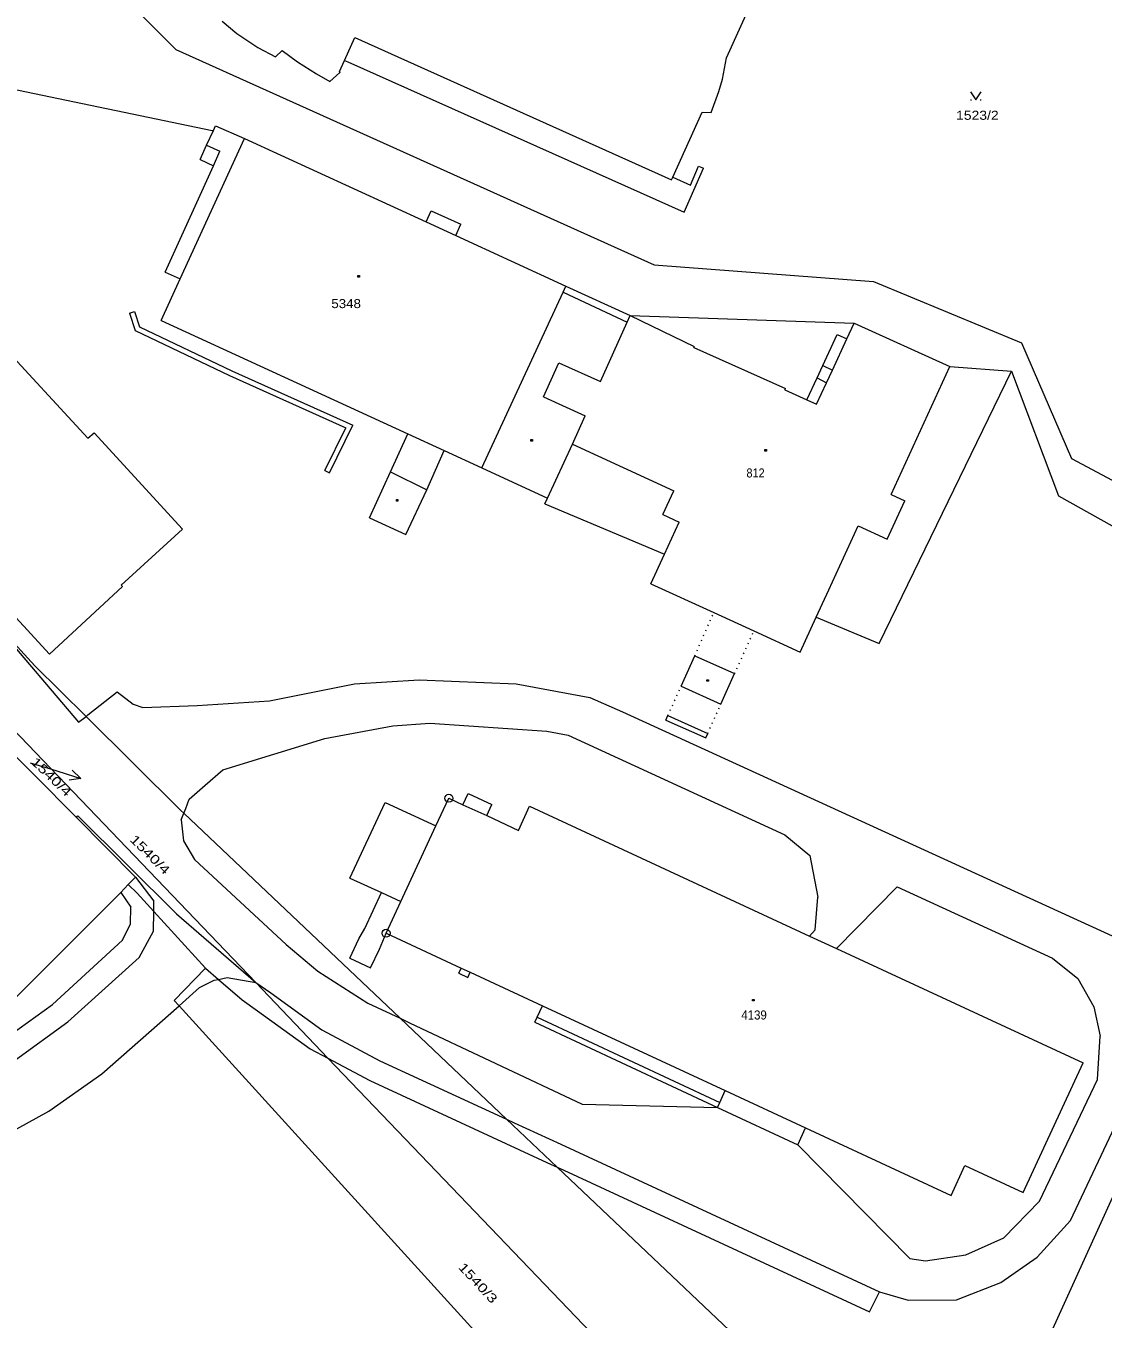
# Model space of a CAD drawing. Extents: x -630464 to -630140, y -1004543 to -1004208.
# Drawn here: x -630338.9 to -630237.7, y -1004467.8 to -1004346.3 of the extents above; entities that cross this region are included whole.
import ezdxf

# ---------------------------------------------------------------- set-up
doc = ezdxf.new("R2010")
doc.units = 0
doc.header["$LTSCALE"] = 0.34
doc.linetypes.add('DOTTED', pattern=[1.5, 0.3, -1.2])
for name, color, linetype, lineweight in [('1', 7, 'Continuous', 13), ('13', 7, 'Continuous', 13), ('16', 7, 'Continuous', 13), ('2', 7, 'Continuous', 13), ('23', 7, 'Continuous', 13), ('25', 7, 'Continuous', 13), ('28', 7, 'Continuous', 13)]:
    doc.layers.add(name, color=color, linetype=linetype, lineweight=lineweight)
doc.layers.add('14', color=7, linetype='Continuous')
doc.layers.add('15', color=7, linetype='Continuous')

msp = doc.modelspace()

# ---------------------------------------------------------------- linework, layer by layer
at = {"layer": '1'}
for p, q in [((-630317.08, -1004348.35), (-630315.44, -1004349.23)), ((-630313.38, -1004349.7), (-630311.59, -1004350.82)), ((-630309.41, -1004350.61), (-630309.38, -1004350.69)), ((-630274.53, -1004354.45), (-630273.8, -1004352.49)), ((-630273.8, -1004352.49), (-630273.46, -1004351.32)), ((-630278.12, -1004360.52), (-630275.37, -1004354.41)), ((-630275.37, -1004354.41), (-630274.53, -1004354.45)), ((-630321.38, -1004356.13), (-630321.27, -1004356.15)), ((-630325.81, -1004369.44), (-630321.27, -1004359.46)), ((-630322.52, -1004358.88), (-630321.27, -1004359.46)), ((-630277.04, -1004363.83), (-630275.24, -1004359.68)), ((-630298.51, -1004366.01), (-630298.03, -1004364.95)), ((-630298.51, -1004366.01), (-630288.16, -1004370.77)), ((-630325.81, -1004369.44), (-630324.38, -1004370.09)), ((-630279.86, -1004368.77), (-630259.26, -1004370.34)), ((-630347.29, -1004369.64), (-630333.06, -1004385.05)), ((-630326.17, -1004373.98), (-630324.38, -1004370.09)), ((-630259.26, -1004370.34), (-630245.38, -1004376.09)), ((-630288.16, -1004370.77), (-630282.12, -1004373.51)), ((-630326.17, -1004373.98), (-630303, -1004384.64)), ((-630290.26, -1004381.18), (-630288.81, -1004377.97)), ((-630288.81, -1004377.97), (-630284.91, -1004379.72)), ((-630258.74, -1004404.34), (-630246.3, -1004378.74)), ((-630246.3, -1004378.74), (-630241.9, -1004390.45)), ((-630290.26, -1004381.18), (-630286.34, -1004382.94)), ((-630287.55, -1004385.62), (-630286.34, -1004382.94)), ((-630299.6, -1004386.2), (-630296.05, -1004387.84)), ((-630296.05, -1004387.84), (-630289.89, -1004390.67)), ((-630290.14, -1004391.22), (-630278.9, -1004395.93)), ((-630241.9, -1004390.45), (-630233.45, -1004395.18)), ((-630306.62, -1004392.53), (-630303.19, -1004394.11)), ((-630329.92, -1004398.86), (-630324.18, -1004393.59)), ((-630345.07, -1004396.18), (-630336.65, -1004405.35)), ((-630280.18, -1004398.74), (-630278.9, -1004395.93)), ((-630354.15, -1004397.75), (-630317.27, -1004436.17)), ((-630336.65, -1004405.35), (-630329.81, -1004398.97)), ((-630329.92, -1004398.86), (-630329.81, -1004398.97)), ((-630280.18, -1004398.74), (-630274.27, -1004401.44)), ((-630266.14, -1004405.15), (-630264.65, -1004401.87)), ((-630264.65, -1004401.87), (-630258.74, -1004404.34)), ((-630270.5, -1004403.16), (-630266.14, -1004405.15)), ((-630277.34, -1004408.36), (-630276.05, -1004405.49)), ((-630273.6, -1004410.04), (-630272.31, -1004407.17)), ((-630278.77, -1004411.53), (-630278.58, -1004411.11)), ((-630278.77, -1004411.53), (-630275.03, -1004413.21)), ((-630275.03, -1004413.21), (-630274.84, -1004412.79)), ((-630308.44, -1004426.37), (-630305.13, -1004419.28)), ((-630295.6, -1004420.51), (-630295.12, -1004419.47)), ((-630329.26, -1004426.99), (-630328.57, -1004426.3)), ((-630308.44, -1004426.37), (-630305.48, -1004427.74)), ((-630308.46, -1004433.9), (-630307.61, -1004432.09)), ((-630308.46, -1004433.9), (-630306.51, -1004434.81)), ((-630298.21, -1004435.31), (-630297.99, -1004434.83)), ((-630317.27, -1004436.17), (-630310.52, -1004443.29)), ((-630317.12, -1004438.84), (-630312.18, -1004442.41)), ((-630291.08, -1004439.91), (-630273.92, -1004447.92)), ((-630245.22, -1004455.91), (-630239.59, -1004443.74)), ((-630273.92, -1004447.92), (-630266.39, -1004451.43)), ((-630266.39, -1004451.43), (-630265.65, -1004449.83)), ((-630265.65, -1004449.83), (-630251.98, -1004456.18)), ((-630251.98, -1004456.18), (-630250.68, -1004453.38)), ((-630250.68, -1004453.38), (-630245.22, -1004455.91))]:
    msp.add_line(p, q, dxfattribs=at)
at = {"layer": '1', "linetype": 'DOTTED'}
for p, q in [((-630276.05, -1004405.49), (-630274.27, -1004401.44)), ((-630272.31, -1004407.17), (-630270.5, -1004403.16)), ((-630278.58, -1004411.11), (-630277.34, -1004408.36)), ((-630274.84, -1004412.79), (-630273.6, -1004410.04))]:
    msp.add_line(p, q, dxfattribs=at)
at = {"layer": '1'}
for points in [[(-630329.82, -1004343.46), (-630324.8, -1004348.52), (-630279.86, -1004368.77)], [(-630273.46, -1004351.32), (-630273.07, -1004349.32), (-630270.17, -1004342.86)], [(-630320.45, -1004345.86), (-630319.08, -1004347.02), (-630317.08, -1004348.35)], [(-630315.44, -1004349.23), (-630314.81, -1004348.63), (-630313.38, -1004349.7)], [(-630309.41, -1004350.61), (-630308.94, -1004349.56), (-630308.64, -1004349.69), (-630277.04, -1004363.83)], [(-630311.59, -1004350.82), (-630310.34, -1004351.54), (-630309.38, -1004350.69)], [(-630342.25, -1004354.67), (-630341.06, -1004352.03), (-630321.38, -1004356.13)], [(-630322.52, -1004358.88), (-630321.9, -1004357.53), (-630321.27, -1004356.15), (-630321.07, -1004355.72), (-630318.33, -1004356.9), (-630301.28, -1004364.74)], [(-630278.12, -1004360.52), (-630276.45, -1004361.29), (-630275.7, -1004359.49), (-630275.24, -1004359.68)], [(-630301.28, -1004364.74), (-630300.8, -1004363.68), (-630298.03, -1004364.95)], [(-630284.91, -1004379.72), (-630282.41, -1004374.16), (-630282.12, -1004373.51), (-630261.07, -1004374.23)], [(-630261.07, -1004374.23), (-630252.1, -1004378.3), (-630246.3, -1004378.74)], [(-630245.38, -1004376.09), (-630240.68, -1004386.95), (-630232.16, -1004391.49)], [(-630360.7, -1004381.74), (-630343.98, -1004399.94), (-630338.03, -1004406.42), (-630333.23, -1004411.18), (-630324.32, -1004420.02), (-630324.04, -1004420.28), (-630303.74, -1004439.53), (-630293.73, -1004449.03), (-630288.99, -1004453.52), (-630254.82, -1004485.91)], [(-630333.06, -1004385.05), (-630332.48, -1004384.54), (-630324.18, -1004393.59)], [(-630306.62, -1004392.53), (-630304.63, -1004388.2), (-630303, -1004384.64)], [(-630303.19, -1004394.11), (-630301.23, -1004389.9), (-630299.6, -1004386.2)], [(-630290.14, -1004391.22), (-630289.89, -1004390.67), (-630287.55, -1004385.62)], [(-630354.36, -1004410.83), (-630344.06, -1004410.7), (-630342.12, -1004412.66), (-630334.14, -1004420.69), (-630328.57, -1004426.3)], [(-630305.13, -1004419.28), (-630300.37, -1004421.48), (-630299.15, -1004418.88), (-630297.83, -1004419.49)], [(-630297.83, -1004419.49), (-630297.34, -1004418.44), (-630295.12, -1004419.47)], [(-630295.6, -1004420.51), (-630292.6, -1004421.9), (-630291.57, -1004419.61), (-630265.27, -1004431.82)], [(-630254.2, -1004486.47), (-630251.14, -1004485.59), (-630248.99, -1004483.18), (-630220.7, -1004420.89), (-630209.99, -1004425.12)], [(-630355.83, -1004426.26), (-630342.18, -1004439.92), (-630329.96, -1004427.73), (-630329.26, -1004426.99), (-630328.44, -1004427.8), (-630326.87, -1004429.52), (-630322.01, -1004434.84)], [(-630307.61, -1004432.09), (-630307.04, -1004431.12), (-630305.48, -1004427.74)], [(-630306.51, -1004434.81), (-630305.67, -1004433.06), (-630305.05, -1004431.55), (-630297.99, -1004434.83)], [(-630265.27, -1004431.82), (-630262.73, -1004433), (-630239.59, -1004443.74)], [(-630324.95, -1004437.86), (-630322.01, -1004434.84), (-630320.8, -1004435.89), (-630318.56, -1004437.81), (-630317.12, -1004438.84)], [(-630298.21, -1004435.31), (-630297.38, -1004435.71), (-630297.15, -1004435.22), (-630290.37, -1004438.37)], [(-630324.95, -1004437.86), (-630324.49, -1004438.36), (-630272.19, -1004495.93)], [(-630291.08, -1004439.91), (-630290.87, -1004439.45), (-630290.37, -1004438.37)], [(-630312.18, -1004442.41), (-630310.52, -1004443.29), (-630276.34, -1004478.97)]]:
    msp.add_lwpolyline(points, dxfattribs=at)
at = {"layer": '13'}
msp.add_line((-630338.47, -1004415.54), (-630336.58, -1004416.12), dxfattribs=at)
at = {"layer": '16'}
msp.add_line((-630333.713, -1004417.005), (-630334.816, -1004417.187), dxfattribs=at)
msp.add_lwpolyline([(-630336.58, -1004416.12), (-630333.713, -1004417.005), (-630334.521, -1004416.232)], dxfattribs=at)
at = {"layer": '2'}
for p, q in [((-630308.94, -1004349.56), (-630307.98, -1004347.41)), ((-630307.98, -1004347.41), (-630278.24, -1004360.78)), ((-630324.38, -1004370.09), (-630318.33, -1004356.9)), ((-630321.9, -1004357.53), (-630320.65, -1004358.1)), ((-630321.27, -1004359.46), (-630320.65, -1004358.1)), ((-630278.24, -1004360.78), (-630278.12, -1004360.52)), ((-630301.28, -1004364.74), (-630298.51, -1004366.01)), ((-630296.05, -1004387.84), (-630288.42, -1004371.32)), ((-630288.42, -1004371.32), (-630288.16, -1004370.77)), ((-630288.42, -1004371.32), (-630282.41, -1004374.16)), ((-630329.15, -1004373.31), (-630328.67, -1004373.16)), ((-630329.15, -1004373.31), (-630328.61, -1004374.94)), ((-630328.67, -1004373.16), (-630328.2, -1004374.58)), ((-630282.12, -1004373.51), (-630276.11, -1004376.45)), ((-630328.61, -1004374.94), (-630319.75, -1004379.16)), ((-630328.2, -1004374.58), (-630319.54, -1004378.71)), ((-630264.03, -1004378.23), (-630262.67, -1004375.3)), ((-630276.14, -1004376.52), (-630276.11, -1004376.45)), ((-630276.14, -1004376.52), (-630267.54, -1004380.39)), ((-630263.12, -1004378.65), (-630261.76, -1004375.72)), ((-630319.75, -1004379.16), (-630308.84, -1004384.07)), ((-630319.54, -1004378.71), (-630308.16, -1004383.83)), ((-630264.57, -1004379.38), (-630264.03, -1004378.23)), ((-630264.03, -1004378.23), (-630263.12, -1004378.65)), ((-630263.68, -1004379.84), (-630263.12, -1004378.65)), ((-630257.61, -1004390.35), (-630252.1, -1004378.3)), ((-630267.59, -1004380.51), (-630267.54, -1004380.39)), ((-630265.52, -1004381.44), (-630264.57, -1004379.38)), ((-630264.61, -1004381.85), (-630263.68, -1004379.84)), ((-630264.57, -1004379.38), (-630263.68, -1004379.84)), ((-630267.59, -1004380.51), (-630265.52, -1004381.44)), ((-630265.52, -1004381.44), (-630264.61, -1004381.85)), ((-630310.8, -1004388.07), (-630308.84, -1004384.07)), ((-630310.35, -1004388.29), (-630308.16, -1004383.83)), ((-630303, -1004384.64), (-630299.6, -1004386.2)), ((-630287.55, -1004385.62), (-630278.02, -1004390.01)), ((-630310.8, -1004388.07), (-630310.35, -1004388.29)), ((-630304.63, -1004388.2), (-630301.23, -1004389.9)), ((-630279.04, -1004392.23), (-630278.02, -1004390.01)), ((-630257.98, -1004394.53), (-630256.34, -1004390.93)), ((-630257.61, -1004390.35), (-630256.34, -1004390.93)), ((-630279.04, -1004392.23), (-630277.53, -1004392.93)), ((-630278.9, -1004395.93), (-630277.53, -1004392.93)), ((-630263.46, -1004399.28), (-630260.72, -1004393.28)), ((-630260.72, -1004393.28), (-630257.98, -1004394.53)), ((-630264.65, -1004401.87), (-630263.46, -1004399.28)), ((-630343.98, -1004399.94), (-630333.94, -1004411.74)), ((-630274.27, -1004401.44), (-630270.5, -1004403.16)), ((-630276.05, -1004405.49), (-630272.31, -1004407.17)), ((-630316, -1004409.71), (-630308.01, -1004408.14)), ((-630308.01, -1004408.14), (-630301.95, -1004407.74)), ((-630301.95, -1004407.74), (-630292.84, -1004408.14)), ((-630292.84, -1004408.14), (-630285.92, -1004409.4)), ((-630277.34, -1004408.36), (-630273.6, -1004410.04)), ((-630330.29, -1004408.89), (-630328.8, -1004410.03)), ((-630285.92, -1004409.4), (-630282.83, -1004410.76)), ((-630328.8, -1004410.03), (-630327.91, -1004410.36)), ((-630327.91, -1004410.36), (-630322.78, -1004410.17)), ((-630322.78, -1004410.17), (-630316, -1004409.71)), ((-630282.83, -1004410.76), (-630229.71, -1004435.08)), ((-630304.42, -1004412.08), (-630300.95, -1004411.82)), ((-630300.95, -1004411.82), (-630289.94, -1004412.58)), ((-630278.58, -1004411.11), (-630274.84, -1004412.79)), ((-630310.8, -1004413.27), (-630304.42, -1004412.08)), ((-630289.94, -1004412.58), (-630287.94, -1004412.94)), ((-630287.94, -1004412.94), (-630267.61, -1004422.3)), ((-630320.39, -1004416.22), (-630310.8, -1004413.27)), ((-630322.05, -1004417.66), (-630320.39, -1004416.22)), ((-630324.28, -1004420.89), (-630324.04, -1004420.28)), ((-630324.04, -1004420.28), (-630323.87, -1004419.84)), ((-630297.83, -1004419.49), (-630295.6, -1004420.51)), ((-630324.28, -1004420.89), (-630324.09, -1004422.87)), ((-630303.67, -1004428.58), (-630300.37, -1004421.48)), ((-630324.09, -1004422.87), (-630323.03, -1004424.64)), ((-630267.61, -1004422.3), (-630265.25, -1004424.24)), ((-630323.03, -1004424.64), (-630314.43, -1004432.6)), ((-630265.25, -1004424.24), (-630264.51, -1004428.18)), ((-630328.57, -1004426.3), (-630326.86, -1004428.54)), ((-630329.96, -1004427.73), (-630329.01, -1004429.11)), ((-630305.48, -1004427.74), (-630303.67, -1004428.58)), ((-630262.73, -1004433), (-630257.05, -1004427.2)), ((-630257.05, -1004427.2), (-630242.46, -1004433.9)), ((-630305.05, -1004431.55), (-630303.67, -1004428.58)), ((-630264.74, -1004431.22), (-630264.51, -1004428.18)), ((-630329.05, -1004430.67), (-630329.01, -1004429.11)), ((-630324.74, -1004429.73), (-630317.27, -1004436.17)), ((-630329.8, -1004432.2), (-630329.05, -1004430.67)), ((-630328.25, -1004433.85), (-630326.88, -1004431.35)), ((-630265.27, -1004431.82), (-630264.74, -1004431.22)), ((-630336.37, -1004438.25), (-630329.8, -1004432.2)), ((-630314.43, -1004432.6), (-630311.46, -1004435.11)), ((-630334.95, -1004439.88), (-630328.25, -1004433.85)), ((-630311.46, -1004435.11), (-630306.76, -1004438.11)), ((-630297.99, -1004434.83), (-630297.15, -1004435.22)), ((-630242.46, -1004433.9), (-630240.08, -1004435.8)), ((-630240.77, -1004458.53), (-630229.71, -1004435.08)), ((-630322.57, -1004436.66), (-630321.18, -1004435.96)), ((-630319.96, -1004435.72), (-630317.27, -1004436.17)), ((-630317.27, -1004436.17), (-630315.88, -1004437.16)), ((-630240.08, -1004435.8), (-630238.58, -1004438.48)), ((-630324.49, -1004438.36), (-630322.57, -1004436.66)), ((-630315.88, -1004437.16), (-630311.07, -1004440.63)), ((-630341.08, -1004441.64), (-630336.37, -1004438.25)), ((-630331.74, -1004444.77), (-630324.49, -1004438.36)), ((-630306.76, -1004438.11), (-630303.74, -1004439.53)), ((-630290.37, -1004438.37), (-630273.19, -1004446.34)), ((-630238.58, -1004438.48), (-630237.97, -1004441.24)), ((-630339.86, -1004443.44), (-630334.95, -1004439.88)), ((-630303.74, -1004439.53), (-630302.84, -1004439.96)), ((-630302.84, -1004439.96), (-630286.62, -1004447.61)), ((-630290.87, -1004439.45), (-630273.71, -1004447.46)), ((-630311.07, -1004440.63), (-630305.64, -1004443.53)), ((-630238.23, -1004445.29), (-630237.97, -1004441.24)), ((-630310.52, -1004443.29), (-630306.57, -1004445.4)), ((-630305.64, -1004443.53), (-630293.73, -1004449.03)), ((-630336.72, -1004448.26), (-630331.74, -1004444.77)), ((-630306.57, -1004445.4), (-630289.53, -1004453.27)), ((-630243.67, -1004456.74), (-630238.23, -1004445.29)), ((-630273.71, -1004447.46), (-630273.19, -1004446.34)), ((-630273.19, -1004446.34), (-630265.65, -1004449.83)), ((-630342.07, -1004451.2), (-630336.72, -1004448.26)), ((-630286.62, -1004447.61), (-630273.92, -1004447.92)), ((-630273.92, -1004447.92), (-630273.71, -1004447.46)), ((-630293.73, -1004449.03), (-630293.01, -1004449.36)), ((-630293.01, -1004449.36), (-630288.65, -1004451.37)), ((-630288.65, -1004451.37), (-630258.71, -1004465.25)), ((-630266.39, -1004451.43), (-630255.87, -1004462.11)), ((-630289.53, -1004453.27), (-630288.99, -1004453.52)), ((-630288.99, -1004453.52), (-630288.35, -1004453.81)), ((-630288.35, -1004453.81), (-630259.63, -1004467.13)), ((-630247.04, -1004460.16), (-630243.67, -1004456.74)), ((-630243.9, -1004462), (-630240.77, -1004458.53)), ((-630250.58, -1004461.76), (-630247.04, -1004460.16)), ((-630254.38, -1004462.32), (-630250.58, -1004461.76)), ((-630255.87, -1004462.11), (-630254.38, -1004462.32)), ((-630247.31, -1004464.36), (-630243.9, -1004462)), ((-630251.48, -1004465.99), (-630247.31, -1004464.36)), ((-630256, -1004466.02), (-630251.48, -1004465.99))]:
    msp.add_line(p, q, dxfattribs=at)
for points in [[(-630262.67, -1004375.3), (-630261.76, -1004375.72), (-630261.07, -1004374.23)], [(-630333.94, -1004411.74), (-630333.23, -1004411.18), (-630333.06, -1004411.05), (-630330.29, -1004408.89)], [(-630323.87, -1004419.84), (-630323.53, -1004418.97), (-630322.05, -1004417.66)], [(-630334.14, -1004420.69), (-630333.99, -1004420.53), (-630324.74, -1004429.73)], [(-630326.88, -1004431.35), (-630326.87, -1004429.52), (-630326.86, -1004428.54)], [(-630321.18, -1004435.96), (-630320.8, -1004435.89), (-630319.96, -1004435.72)], [(-630259.63, -1004467.13), (-630258.71, -1004465.25), (-630256, -1004466.02)]]:
    msp.add_lwpolyline(points, dxfattribs=at)
at = {"layer": '23'}
for p, q in [((-630250.15, -1004353.25), (-630250.05, -1004353.25)), ((-630249.25, -1004353.25), (-630249.15, -1004353.25))]:
    msp.add_line(p, q, dxfattribs=at)
msp.add_lwpolyline([(-630250.15, -1004352.5), (-630249.65, -1004353.25), (-630249.15, -1004352.5)], dxfattribs=at)
at = {"layer": '25'}
for points in [[(-630307.7, -1004369.76), (-630307.55, -1004369.76), (-630307.55, -1004369.91), (-630307.7, -1004369.91)], [(-630291.45, -1004385.18), (-630291.3, -1004385.18), (-630291.3, -1004385.33), (-630291.45, -1004385.33)], [(-630269.46, -1004386.11), (-630269.31, -1004386.11), (-630269.31, -1004386.26), (-630269.46, -1004386.26)], [(-630304.08, -1004390.8), (-630303.93, -1004390.8), (-630303.93, -1004390.95), (-630304.08, -1004390.95)], [(-630274.93, -1004407.74), (-630274.78, -1004407.74), (-630274.78, -1004407.89), (-630274.93, -1004407.89)], [(-630270.63, -1004437.77), (-630270.48, -1004437.77), (-630270.48, -1004437.92), (-630270.63, -1004437.92)]]:
    msp.add_lwpolyline(points, close=True, dxfattribs=at)
at = {"layer": '28'}
for centre, radius in [((-630299.15, -1004418.88), 0.375), ((-630299.15, -1004418.88), 0.005), ((-630305.05, -1004431.55), 0.375), ((-630305.05, -1004431.55), 0.005)]:
    msp.add_circle(centre, radius, dxfattribs=at)

# ---------------------------------------------------------------- texts
at = {"layer": '14', "width": 1.15}
msp.add_text('1523/2', height=0.85, dxfattribs=at).set_placement((-630251.51, -1004355.14))
at = {"layer": '14', "width": 1.35}
for s, rotation, p in [('1540/4', 316.23, (-630338.47, -1004415.54)), ('1540/3', 313.099, (-630298.33, -1004462.98))]:
    msp.add_text(s, height=0.85, rotation=rotation, dxfattribs=at).set_placement(p)
at = {"layer": '15'}
for s, width, p in [('5348', 1.1, (-630310.19, -1004372.83)), ('812', 0.9, (-630271.2, -1004388.74)), ('4139', 0.95, (-630271.69, -1004439.66))]:
    msp.add_text(s, height=0.85, dxfattribs=dict(at, width=width)).set_placement(p)
at = {"layer": '16', "width": 1.35}
msp.add_text('1540/4', height=0.85, rotation=315.265, dxfattribs=at).set_placement((-630329.186, -1004422.815))

doc.saveas('drawing.dxf')
